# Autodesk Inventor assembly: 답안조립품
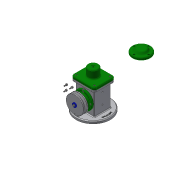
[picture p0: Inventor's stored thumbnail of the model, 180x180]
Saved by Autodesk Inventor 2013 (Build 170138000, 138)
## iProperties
Created: 2019-08
Part Number: 답안조립품
Document SubType Name: Assembly
Designer: Administrator
Author: Administrator
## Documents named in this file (18)
- C:\Users\Administrator\Desktop\490804V1038\답안조립품.iam
- C:\Users\Administrator\Desktop\490804V1038\본체.ipt
- C:\Users\Administrator\Desktop\490804V1038\E-링.ipt
- C:\Users\Administrator\Desktop\490804V1038\V-벨트풀리.ipt
- C:\Users\Administrator\Desktop\490804V1038\덮개.ipt
- C:\Users\Administrator\Desktop\490804V1038\뒤커버.ipt
- C:\Users\Administrator\Desktop\490804V1038\링크.ipt
- C:\Users\Administrator\Desktop\490804V1038\베어링 17 x 40 x 12.ipt
- C:\Users\Administrator\Desktop\490804V1038\볼트 M4 x 8.ipt
- C:\Users\Administrator\Desktop\490804V1038\볼트 M4 x 10.ipt
- C:\Users\Administrator\Desktop\490804V1038\슬라이더.ipt
- C:\Users\Administrator\Desktop\490804V1038\앞커버.ipt
- C:\Users\Administrator\Desktop\490804V1038\오일 실 17 30 8.ipt
- C:\Users\Administrator\Desktop\490804V1038\와셔 4x16.ipt
- C:\Users\Administrator\Desktop\490804V1038\클레비스 핀 6 x 22.ipt
- 클레비스 핀 6 x 22.ipt
- C:\Users\Administrator\Desktop\490804V1038\키 4 x 4 x 12.ipt
- C:\Users\Administrator\Desktop\490804V1038\편심축.ipt
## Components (2 placed, 2 different names)
1. E-링:1
2. V-벨트풀리:1
